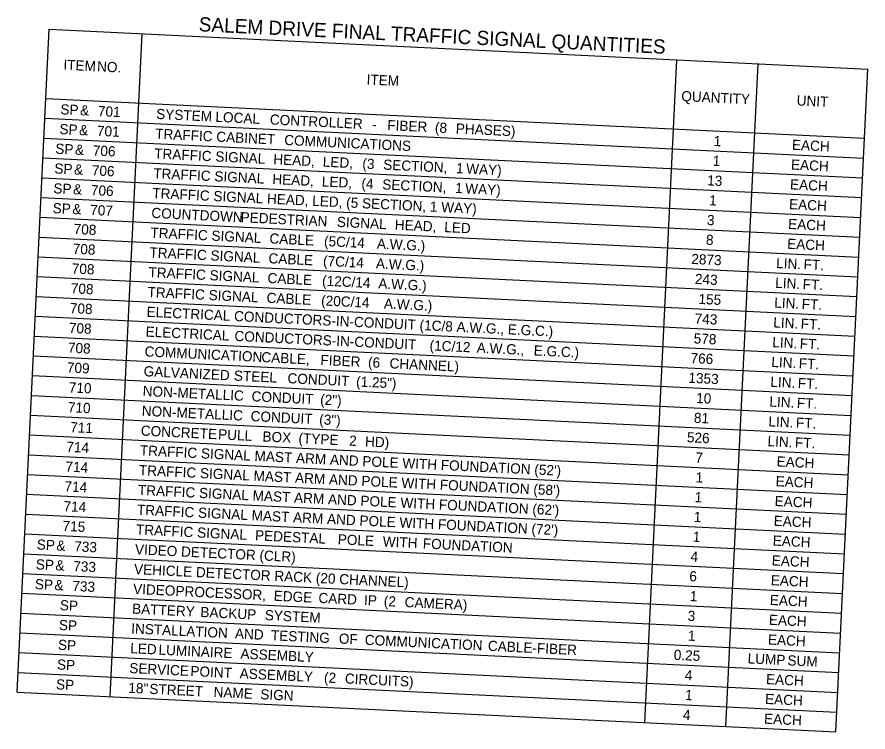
# Model space of a CAD drawing. Extents: x 661030 to 662601, y 642184 to 643065.
# Drawn here: x 661384.1 to 661586.8, y 642600.1 to 642770.6 of the extents above; entities that cross this region are included whole.
import ezdxf

# ---------------------------------------------------------------- set-up
doc = ezdxf.new("R2010")
doc.units = 0
doc.layers.add('R_Dimension', color=7, linetype='Continuous')

msp = doc.modelspace()

# ---------------------------------------------------------------- linework, layer by layer
at = {"layer": 'R_Dimension'}
for p, q in [((661384.08, 642609.62), (661391.75, 642767.64)), ((661391.75, 642767.64), (661586.84, 642758.16)), ((661406.25, 642608.54), (661413.92, 642766.56)), ((661533.65, 642602.35), (661541.32, 642760.37)), ((661552.99, 642601.41), (661560.66, 642759.43)), ((661579.17, 642600.14), (661586.84, 642758.16)), ((661390.95, 642751.13), (661586.04, 642741.65)), ((661390.72, 642746.41), (661585.81, 642736.94)), ((661390.49, 642741.69), (661585.58, 642732.22)), ((661390.26, 642736.98), (661585.35, 642727.5)), ((661390.03, 642732.26), (661585.12, 642722.78)), ((661389.8, 642727.54), (661584.89, 642718.07)), ((661389.57, 642722.82), (661584.67, 642713.35)), ((661389.35, 642718.11), (661584.44, 642708.63)), ((661389.12, 642713.39), (661584.21, 642703.92)), ((661388.89, 642708.67), (661583.98, 642699.2)), ((661388.66, 642703.96), (661583.75, 642694.48)), ((661388.43, 642699.24), (661583.52, 642689.77)), ((661388.2, 642694.52), (661583.29, 642685.05)), ((661387.97, 642689.8), (661583.06, 642680.33)), ((661387.74, 642685.09), (661582.83, 642675.61)), ((661387.51, 642680.37), (661582.6, 642670.9)), ((661387.28, 642675.65), (661582.37, 642666.18)), ((661387.06, 642670.94), (661582.15, 642661.46)), ((661386.83, 642666.22), (661581.92, 642656.75)), ((661386.6, 642661.5), (661581.69, 642652.03)), ((661386.37, 642656.79), (661581.46, 642647.31)), ((661386.14, 642652.07), (661581.23, 642642.6)), ((661385.91, 642647.35), (661581, 642637.88)), ((661385.68, 642642.63), (661580.77, 642633.16)), ((661385.45, 642637.92), (661580.54, 642628.44)), ((661385.22, 642633.2), (661580.31, 642623.73)), ((661384.99, 642628.48), (661580.08, 642619.01)), ((661384.76, 642623.77), (661579.86, 642614.29)), ((661384.54, 642619.05), (661579.63, 642609.58)), ((661384.31, 642614.33), (661579.4, 642604.86)), ((661384.08, 642609.62), (661579.17, 642600.14))]:
    msp.add_line(p, q, dxfattribs=at)

# ---------------------------------------------------------------- texts
for s, height, p in [('SALEM DRIVE FINAL TRAFFIC SIGNAL QUANTITIES', 3.3906, (661427.32, 642767.17)), ('ITEM', 2.422, (661395.09, 642757.99)), (' NO.', 2.422, (661402.21, 642757.64)), ('ITEM', 2.422, (661467.33, 642754.48)), ('QUANTITY', 2.422, (661542.31, 642750.53)), ('UNIT', 2.422, (661569.8, 642749.5)), ('SP', 2.422, (661394.37, 642747.38)), (' &', 2.422, (661398.16, 642747.2)), (' 701', 2.422, (661402.4, 642746.99)), ('SYSTEM', 2.422, (661417.19, 642746.28)), (' LOCAL', 2.422, (661430.41, 642745.63)), (' CONTROLLER', 2.4218, (661443.38, 642745)), (' FIBER', 2.422, (661471.36, 642743.65)), ('SP', 2.422, (661394.14, 642742.67)), (' &', 2.422, (661397.93, 642742.48)), (' 701', 2.422, (661402.17, 642742.28)), ('TRAFFIC', 2.422, (661416.96, 642741.56)), (' -', 2.422, (661467.76, 642743.82)), (' (8', 2.422, (661482.71, 642743.09)), (' PHASES)', 2.422, (661487.68, 642742.85)), (' CABINET', 2.422, (661430.62, 642740.9)), (' COMMUNICATIONS', 2.4218, (661446.81, 642740.11)), ('1', 2.42, (661550.02, 642739.83)), ('SP', 2.422, (661393.16, 642737.99)), (' &', 2.422, (661396.95, 642737.8)), (' 706', 2.422, (661401.19, 642737.6)), ('EACH', 2.422, (661568.68, 642738.92)), ('TRAFFIC', 2.422, (661416.73, 642736.84)), (' SIGNAL', 2.422, (661430.39, 642736.18)), (' HEAD,', 2.422, (661444.2, 642735.51)), (' LED,', 2.422, (661455.99, 642734.94)), (' (3', 2.422, (661465.42, 642734.48)), (' SECTION,', 2.422, (661470.39, 642734.24)), ('1', 2.42, (661549.79, 642735.11)), ('EACH', 2.422, (661568.45, 642734.2)), ('SP', 2.422, (661392.93, 642733.27)), (' &', 2.422, (661396.72, 642733.09)), (' 706', 2.422, (661400.96, 642732.88)), ('TRAFFIC', 2.422, (661416.5, 642732.12)), (' SIGNAL', 2.422, (661430.16, 642731.46)), (' 1', 2.422, (661487.74, 642733.39)), (' WAY)', 2.422, (661490.16, 642733.28)), (' HEAD,', 2.422, (661443.97, 642730.79)), (' LED,', 2.422, (661455.76, 642730.22)), (' (4', 2.422, (661465.19, 642729.76)), (' SECTION,', 2.422, (661470.16, 642729.52)), ('13', 2.422, (661548.47, 642730.44)), ('EACH', 2.422, (661568.22, 642729.49)), ('SP', 2.422, (661392.7, 642728.55)), (' &', 2.422, (661396.49, 642728.37)), (' 706', 2.422, (661400.74, 642728.16)), ('TRAFFIC SIGNAL HEAD, LED, (5 SECTION, 1 WAY)', 2.4218, (661416.27, 642727.41)), (' 1', 2.422, (661487.51, 642728.68)), (' WAY)', 2.422, (661489.93, 642728.56)), ('1', 2.42, (661548.93, 642725.69)), ('SP', 2.422, (661392.53, 642723.83)), (' &', 2.422, (661396.33, 642723.65)), (' 707', 2.422, (661400.57, 642723.44)), ('EACH', 2.422, (661567.99, 642724.77)), ('COUNTDOWN', 2.422, (661416.05, 642722.69)), (' PEDESTRIAN', 2.4218, (661436.41, 642721.7)), (' SIGNAL', 2.422, (661459.34, 642720.59)), (' HEAD,', 2.422, (661473.15, 642719.92)), (' LED', 2.422, (661484.94, 642719.34)), ('3', 2.42, (661548.42, 642720.99)), ('EACH', 2.422, (661567.77, 642720.05)), ('708', 2.422, (661397.53, 642718.86)), ('TRAFFIC', 2.422, (661415.82, 642717.97)), (' SIGNAL', 2.422, (661429.47, 642717.31)), (' CABLE', 2.422, (661443.28, 642716.64)), (' (5C/14', 2.422, (661456.29, 642716.01)), (' A.W.G.)', 2.422, (661468.88, 642715.4)), ('8', 2.42, (661548.19, 642716.27)), ('EACH', 2.422, (661567.54, 642715.33)), ('708', 2.422, (661397.31, 642714.14)), ('TRAFFIC', 2.422, (661415.59, 642713.26)), (' SIGNAL', 2.422, (661429.24, 642712.59)), (' CABLE', 2.422, (661443.05, 642711.92)), (' (7C/14', 2.422, (661456.06, 642711.29)), ('2873', 2.422, (661544.7, 642711.71)), ('708', 2.422, (661397.08, 642709.43)), (' A.W.G.)', 2.422, (661468.65, 642710.68)), ('LIN.', 2.422, (661564.92, 642710.73)), (' FT.', 2.422, (661570.55, 642710.46)), ('TRAFFIC', 2.422, (661415.36, 642708.54)), (' SIGNAL', 2.422, (661429.02, 642707.88)), (' CABLE', 2.422, (661442.82, 642707.21)), (' (12C/14', 2.422, (661455.83, 642706.57)), (' A.W.G.)', 2.422, (661469.22, 642705.92)), ('243', 2.422, (661545.56, 642706.95)), ('LIN.', 2.422, (661564.69, 642706.02)), (' FT.', 2.422, (661570.33, 642705.74)), ('708', 2.422, (661396.85, 642704.71)), ('TRAFFIC', 2.422, (661415.13, 642703.82)), (' SIGNAL', 2.422, (661428.79, 642703.16)), (' CABLE', 2.422, (661442.6, 642702.49)), (' (20C/14', 2.422, (661455.6, 642701.86)), (' A.W.G.)', 2.422, (661470.56, 642701.13)), ('155', 2.422, (661546.41, 642702.18)), ('LIN.', 2.422, (661564.46, 642701.3)), (' FT.', 2.422, (661570.1, 642701.03)), ('708', 2.422, (661396.62, 642699.99)), ('ELECTRICAL CONDUCTORS-IN-CONDUIT (1C/8 A.W.G., E.G.C.)', 2.4218, (661414.9, 642699.11)), ('743', 2.422, (661545.5, 642697.49)), ('708', 2.422, (661396.39, 642695.28)), ('LIN.', 2.422, (661564.23, 642696.58)), (' FT.', 2.422, (661569.87, 642696.31)), ('ELECTRICAL', 2.422, (661414.67, 642694.39)), (' CONDUCTORS-IN-CONDUIT', 2.4218, (661434.94, 642693.4)), (' (1C/12', 2.422, (661481.45, 642691.15)), ('578', 2.422, (661545.27, 642692.77)), ('LIN.', 2.422, (661564, 642691.87)), (' FT.', 2.422, (661569.64, 642691.59)), ('708', 2.422, (661396.16, 642690.56)), ('COMMUNICATION', 2.4218, (661414.44, 642689.67)), (' A.W.G.,', 2.422, (661492.67, 642690.6)), (' E.G.C.)', 2.422, (661506.25, 642689.94)), (' CABLE,', 2.422, (661441.36, 642688.36)), (' FIBER', 2.422, (661455.43, 642687.68)), (' (6', 2.422, (661466.78, 642687.13)), (' CHANNEL)', 2.422, (661471.89, 642686.88)), ('766', 2.422, (661544.52, 642688.08)), ('LIN.', 2.422, (661563.77, 642687.15)), (' FT.', 2.422, (661569.41, 642686.87)), ('709', 2.422, (661395.92, 642685.84)), ('GALVANIZED', 2.422, (661414.21, 642684.95)), (' STEEL', 2.422, (661434.8, 642683.95)), (' CONDUIT', 2.422, (661447.58, 642683.33)), ('1353', 2.422, (661544.01, 642683.38)), ('710', 2.422, (661396.38, 642681.09)), (' (1.25")', 2.422, (661463.93, 642682.54)), ('LIN.', 2.422, (661563.54, 642682.43)), (' FT.', 2.422, (661569.18, 642682.16)), ('NON-METALLIC', 2.4218, (661413.98, 642680.24)), (' CONDUIT', 2.422, (661439.03, 642679.02)), (' (2")', 2.422, (661455.37, 642678.23)), ('10', 2.422, (661545.85, 642678.56)), ('LIN.', 2.422, (661563.31, 642677.71)), (' FT.', 2.422, (661568.95, 642677.44)), ('710', 2.422, (661396.15, 642676.38)), ('NON-METALLIC', 2.4218, (661413.76, 642675.52)), (' CONDUIT', 2.422, (661438.8, 642674.3)), (' (3")', 2.422, (661455.14, 642673.51)), ('81', 2.422, (661545.32, 642673.86)), ('LIN.', 2.422, (661563.08, 642673)), (' FT.', 2.422, (661568.72, 642672.72)), ('711', 2.422, (661396.71, 642671.62)), ('CONCRETE', 2.422, (661413.53, 642670.8)), (' PULL', 2.422, (661431.05, 642669.95)), (' BOX', 2.422, (661441.62, 642669.44)), (' (TYPE', 2.422, (661450.21, 642669.02)), ('526', 2.422, (661543.66, 642669.21)), ('714', 2.422, (661395.8, 642666.94)), (' 2', 2.422, (661462.27, 642668.44)), (' HD)', 2.422, (661466.06, 642668.25)), ('LIN.', 2.422, (661562.86, 642668.28)), (' FT.', 2.422, (661568.49, 642668.01)), ("TRAFFIC SIGNAL MAST ARM AND POLE WITH FOUNDATION (52')", 2.4218, (661413.3, 642666.09)), ('7', 2.42, (661545.67, 642664.39)), ('EACH', 2.422, (661565.02, 642663.45)), ('714', 2.422, (661395.57, 642662.22)), ("TRAFFIC SIGNAL MAST ARM AND POLE WITH FOUNDATION (58')", 2.4218, (661413.07, 642661.37)), ('1', 2.42, (661545.72, 642659.66)), ('EACH', 2.422, (661564.79, 642658.73)), ('714', 2.422, (661395.34, 642657.5)), ("TRAFFIC SIGNAL MAST ARM AND POLE WITH FOUNDATION (62')", 2.4218, (661412.84, 642656.65)), ('1', 2.42, (661545.49, 642654.94)), ('714', 2.422, (661395.11, 642652.78)), ('EACH', 2.422, (661564.56, 642654.01)), ("TRAFFIC SIGNAL MAST ARM AND POLE WITH FOUNDATION (72')", 2.4218, (661412.61, 642651.94)), ('1', 2.42, (661545.27, 642650.22)), ('EACH', 2.422, (661564.33, 642649.3)), ('715', 2.422, (661394.88, 642648.07)), ('TRAFFIC', 2.422, (661412.38, 642647.22)), (' SIGNAL', 2.422, (661426.04, 642646.55)), (' PEDESTAL', 2.422, (661439.85, 642645.88)), (' POLE', 2.422, (661459.56, 642644.93)), (' WITH', 2.422, (661470.28, 642644.41)), ('1', 2.42, (661545.04, 642645.5)), ('EACH', 2.422, (661564.1, 642644.58)), ('SP', 2.422, (661388.74, 642643.64)), (' &', 2.422, (661392.53, 642643.45)), (' 733', 2.422, (661396.77, 642643.25)), ('VIDEO DETECTOR (CLR)', 2.4218, (661412.15, 642642.5)), (' FOUNDATION', 2.4218, (661479.83, 642643.94)), ('4', 2.42, (661544.52, 642640.8)), ('SP', 2.422, (661388.51, 642638.92)), (' &', 2.422, (661392.3, 642638.74)), (' 733', 2.422, (661396.54, 642638.53)), ('EACH', 2.422, (661563.87, 642639.86)), ('VEHICLE DETECTOR RACK (20 CHANNEL)', 2.4218, (661411.92, 642637.78)), ('6', 2.42, (661544.23, 642636.09)), ('SP', 2.422, (661388.28, 642634.2)), ('EACH', 2.422, (661563.64, 642635.14)), (' &', 2.422, (661392.07, 642634.02)), (' 733', 2.422, (661396.32, 642633.81)), ('VIDEO', 2.422, (661411.69, 642633.07)), (' PROCESSOR,', 2.4218, (661420.89, 642632.62)), (' EDGE', 2.422, (661444.3, 642631.48)), (' CARD', 2.422, (661454.95, 642630.97)), (' IP', 2.422, (661465.81, 642630.44)), (' (2', 2.422, (661470.53, 642630.21)), ('1', 2.42, (661544.35, 642631.35)), ('EACH', 2.422, (661563.41, 642630.43)), ('SP', 2.422, (661394.24, 642629.19)), ('BATTERY', 2.422, (661411.46, 642628.35)), (' CAMERA)', 2.422, (661475.5, 642629.97)), (' BACKUP', 2.422, (661426.82, 642627.6)), (' SYSTEM', 2.422, (661442.17, 642626.86)), ('3', 2.42, (661543.83, 642626.65)), ('SP', 2.422, (661394.01, 642624.47)), ('EACH', 2.422, (661563.18, 642625.71)), ('INSTALLATION', 2.4218, (661411.24, 642623.63)), (' AND', 2.422, (661435.06, 642622.48)), (' TESTING', 2.422, (661443.63, 642622.06)), ('1', 2.42, (661543.89, 642621.92)), (' OF', 2.422, (661459.82, 642621.27)), (' COMMUNICATION', 2.4218, (661466, 642620.97)), ('EACH', 2.422, (661562.96, 642620.99)), ('SP', 2.422, (661393.78, 642619.75)), ('LED', 2.422, (661411.01, 642618.92)), (' LUMINAIRE', 2.422, (661416.85, 642618.63)), (' CABLE-FIBER', 2.4218, (661495.33, 642619.55)), (' ASSEMBLY', 2.422, (661436.38, 642617.68)), ('0.25', 2.422, (661540.52, 642617.36)), ('LUMP', 2.422, (661558.12, 642616.5)), (' SUM', 2.422, (661566.71, 642616.08)), ('SP', 2.422, (661393.55, 642615.04)), ('SERVICE', 2.422, (661410.78, 642614.2)), (' POINT', 2.422, (661424.45, 642613.53)), (' ASSEMBLY', 2.422, (661436.19, 642612.97)), (' (2', 2.422, (661456.28, 642611.99)), ('4', 2.42, (661543.15, 642612.5)), ('SP', 2.422, (661393.32, 642610.32)), (' CIRCUITS)', 2.422, (661461.25, 642611.75)), ('EACH', 2.422, (661562.5, 642611.56)), ('18"', 2.422, (661410.55, 642609.48)), (' STREET', 2.422, (661414.68, 642609.28)), (' NAME', 2.422, (661429.96, 642608.54)), (' SIGN', 2.422, (661441.1, 642608)), ('1', 2.42, (661543.2, 642607.77)), ('EACH', 2.422, (661562.27, 642606.84)), ('4', 2.42, (661542.69, 642603.07)), ('EACH', 2.422, (661562.04, 642602.13))]:
    msp.add_text(s, height=height, rotation=357.2199, dxfattribs=at).set_placement(p)

doc.saveas('drawing.dxf')
